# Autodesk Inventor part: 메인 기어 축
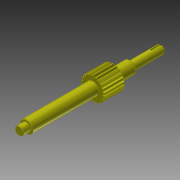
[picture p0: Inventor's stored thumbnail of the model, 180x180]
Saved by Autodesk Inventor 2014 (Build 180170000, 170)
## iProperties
Created: 2018-12
Part Number: 메인 기어 축
Material: 강철, 연강
Document SubType Name: Modeling
Designer: mduedu
Categories: <?xml version="1.0" encoding="UTF-16"?> <MemberInstance><Categories><FamilyTemplate><FamilyTemplateParameter ValueType="xs:double" Id="1" ObjectReferenceKey="da
Density: 7.86 g/cm^3
Mass: 139.66 g
Surface Area: 68.5733 cm^2
Volume: 17.7684 cm^3
Appearance: 노란색
CustomPartVersion: 1
Author: mduedu
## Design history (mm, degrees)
sketch "Sketch1"
  geometry: C1 r 11.3 at (0, 0)
  constraints: 1 centre point
  dimensions: "d0" = 22.6 diameter of C1 (= da_da)
extrude "Extrusion1" new body sketch "Sketch1" distance "d1" = 20 (= da_b); taper "d2" = 0 deg
workplane "Work Plane2"
sketch "Sketch2"
  geometry: C1 r 11.3 at (0, 0) reference; C2 r 10.5 at (0, 0)
  constraints: 1 centre point, 1 coincident
  dimensions: "d3" = 21 diameter of C2 (= da_dw)
feature "피치 지름" sketch "Sketch2" dims "d4" = 10, "d5" = 0
workplane "Work Plane8"
workplane "Work Plane9"
chamfer "모따기1" distance "d49" = 0.5; stored, may be unused: second distance "d50" = 2, angle "d51" = 45 deg
sketch "스케치3"
  geometry: C1 r 6 at (0, 0); 1 further point
  constraints: 1 centre point, 1 coincident
  dimensions: "d52" = 12 diameter of C1
extrude "돌출2" join sketch "스케치3" distance "d53" = 64; taper "d54" = 0 deg
sketch "스케치4"
  geometry: C1 r 4 at (0, 0); 1 further point
  constraints: 1 centre point, 1 coincident
  dimensions: "d55" = 8 diameter of C1
extrude "돌출3" join sketch "스케치4" distance "d56" = 7; taper "d57" = 0 deg
sketch "스케치5"
  geometry: C1 r 6 at (0, 0) reference; C2 r 6 at (0, 0) reference; 1 further point
extrude "돌출4" join sketch "스케치5" distance "d58" = 16; taper "d59" = 0 deg
sketch "스케치6"
  geometry: C1 r 4 at (0, 0); 1 further point
  constraints: 1 centre point, 1 coincident
  dimensions: "d60" = 8 diameter of C1
extrude "돌출5" join sketch "스케치6" distance "d61" = 30; taper "d62" = 0 deg
chamfer "모따기2" distance "d63" = 0.5; stored, may be unused: second distance "d64" = 2, angle "d65" = 45 deg
fillet "모깎기1" dims "d66" = 0.5
feature "스퍼 기어" dims "da_b" = 20, "da_d" = 21, "da_aw" = 31, "da_da" = 22.6, "da_df" = 19.086, "da_dw" = 21, angle "da_beta" = 0 deg, "da_lefttooth" = 0, "da_righttooth" = 0
sketch "스케치7" dims "d67" = 18
  geometry: C1 r 0.25 at (0, -9); 2 further points
  constraints: 2 vertical alignment, 1 centre point, 1 coincident, 2 other
  dimensions: "d68" = 0.5 diameter of C1
extrude "돌출6" join sketch "스케치7" distance "d69" = 0.3; taper "d70" = 0 deg
sketch "스케치8"
  geometry: L1 (4, -16)-(4, -45.5) reference; L2 (3.5, -46)-(-3.5, -46) reference; L3 (4, -46)-(2.8, -46); L4 (2.8, -46)-(2.8, -36); L5 (2.8, -36)-(4, -36); L6 (4, -36)-(4, -46); 1 further point
  constraints: 8 end point, 2 parallel, 2 point on line, 1 horizontal, 1 perpendicular
  dimensions: "d72" = 1.2 distance between parallel lines of L4 L6; "d74" = 10 distance between parallel lines of L5 L3
extrude "돌출7" cut sketch "스케치8" stored distance "d75" = 2; taper "d76" = 0 deg
fillet "모깎기2"
body "Solid1"
body "Srf1"
node "투영된 루프1"
other parameters: "d16" = 31 (= da_aw), "d17" = 0, "d34" = 1.496 (computed from da_z), "d39" = 0, "d41" = 0, "d43" = 31 (= da_aw), "d46" = 31 (= da_aw), "d47" = 0, "d48" = 0
